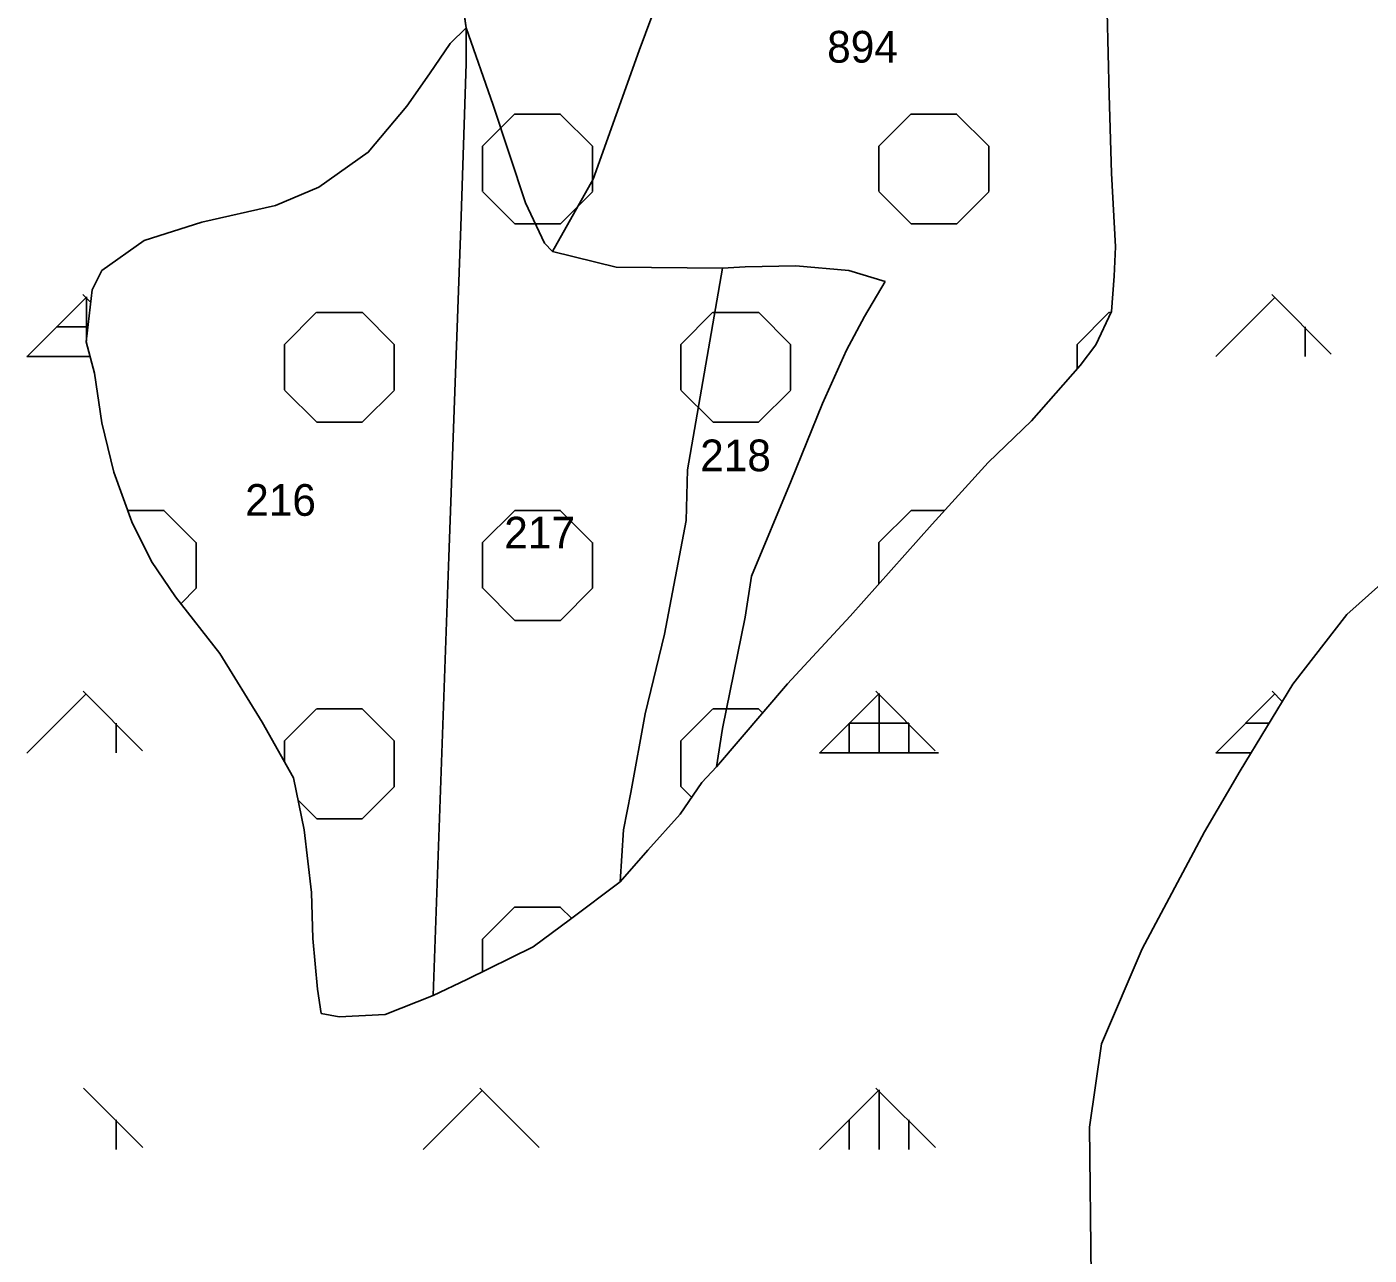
# Model space of a CAD drawing. Extents: x 410727 to 412947, y 4463506 to 4466382.
# Drawn here: x 411905.2 to 412074.5, y 4465822.5 to 4465977.4 of the extents above; entities that cross this region are included whole.
import ezdxf

# ---------------------------------------------------------------- set-up
doc = ezdxf.new("R2010")
doc.units = 0
for name, color, linetype in [('ADAKENARI', 7, 'Continuous'), ('KDS_PARSEL_NO', 7, 'Continuous'), ('KDS_PL', 7, 'Continuous'), ('PL_AYA_AGACLANDIRIL', 7, 'Continuous'), ('PL_AYA_ORMAN', 7, 'Continuous'), ('PL_KA_TARIM_DIGER', 7, 'Continuous'), ('TR_AGACALANI', 7, 'Continuous'), ('TR_ORMAN', 7, 'Continuous')]:
    doc.layers.add(name, color=color, linetype=linetype)

msp = doc.modelspace()

# ---------------------------------------------------------------- linework, layer by layer
at = {"layer": 'ADAKENARI'}
for p, q in [((411956.12, 4466009.18), (411960.57, 4465977.28)), ((412041.72, 4465968.86), (412041.46, 4465979.29)), ((411960.57, 4465977.28), (411958.56, 4465975.32)), ((411958.56, 4465975.32), (411955.98, 4465971.51)), ((411955.98, 4465971.51), (411953.09, 4465967.4)), ((412041.98, 4465958.95), (412041.72, 4465968.86)), ((411953.09, 4465967.4), (411948.23, 4465961.61)), ((411948.23, 4465961.61), (411941.99, 4465957.19)), ((412042.5, 4465949.69), (412041.98, 4465958.95)), ((411941.99, 4465957.19), (411936.52, 4465954.91)), ((411936.52, 4465954.91), (411927.25, 4465952.78)), ((411927.25, 4465952.78), (411919.95, 4465950.49)), ((411919.95, 4465950.49), (411914.63, 4465946.68)), ((412042.32, 4465946), (412042.5, 4465949.69)), ((411914.63, 4465946.68), (411913.42, 4465944.25)), ((412042.01, 4465941.51), (412042.32, 4465946)), ((411913.42, 4465944.25), (411912.66, 4465937.7)), ((412040.04, 4465937.32), (412042.01, 4465941.51)), ((411912.66, 4465937.7), (411913.72, 4465933.74)), ((412038.06, 4465934.73), (412040.04, 4465937.32)), ((412031.91, 4465927.72), (412038.06, 4465934.73)), ((411913.72, 4465933.74), (411914.63, 4465927.49)), ((411914.63, 4465927.49), (411916.15, 4465921.25)), ((412026.43, 4465922.47), (412031.91, 4465927.72)), ((412019.36, 4465914.7), (412026.43, 4465922.47)), ((411916.15, 4465921.25), (411918.43, 4465915)), ((411918.43, 4465915), (411920.87, 4465909.98)), ((412009.03, 4465903.12), (412019.36, 4465914.7)), ((411920.87, 4465909.98), (411923.91, 4465905.56)), ((412075.96, 4465907.16), (412071.69, 4465903.31)), ((411923.91, 4465905.56), (411929.53, 4465898.4)), ((412001.12, 4465894.59), (412009.03, 4465903.12)), ((412001.12, 4465894.59), (412009.03, 4465903.12)), ((412071.69, 4465903.31), (412064.86, 4465894.53)), ((411929.53, 4465898.4), (411934.85, 4465889.72)), ((411992.16, 4465884.09), (412001.12, 4465894.59)), ((412064.86, 4465894.53), (412058.24, 4465883.62)), ((411934.85, 4465889.72), (411938.8, 4465882.72)), ((411990.33, 4465882.11), (411992.16, 4465884.09)), ((412058.24, 4465883.62), (412053.75, 4465875.92)), ((411938.8, 4465882.72), (411940.17, 4465876.17)), ((411987.6, 4465878.15), (411990.33, 4465882.11)), ((411983.49, 4465873.58), (411987.6, 4465878.15)), ((411940.17, 4465876.17), (411941.08, 4465868.25)), ((412053.75, 4465875.92), (412045.85, 4465861.15)), ((411980, 4465869.62), (411983.49, 4465873.58)), ((411973.76, 4465864.9), (411980, 4465869.62)), ((411941.08, 4465868.25), (411941.23, 4465862.46)), ((411969.05, 4465861.39), (411973.76, 4465864.9)), ((411941.23, 4465862.46), (411941.84, 4465856.06)), ((411960.69, 4465857.28), (411969.05, 4465861.39)), ((412045.85, 4465861.15), (412040.72, 4465849.17)), ((411941.84, 4465856.06), (411942.3, 4465853.02)), ((411956.44, 4465855.27), (411960.69, 4465857.28)), ((411950.35, 4465852.87), (411956.44, 4465855.27)), ((411942.3, 4465853.02), (411944.58, 4465852.56)), ((411944.58, 4465852.56), (411950.35, 4465852.87)), ((412040.72, 4465849.17), (412039.23, 4465838.68)), ((412039.23, 4465838.68), (412039.44, 4465819.85))]:
    msp.add_line(p, q, dxfattribs=at)
at = {"layer": 'KDS_PL'}
for p, q in [((411960.57, 4465977.28), (411956.12, 4466009.18)), ((411982.43, 4465974.43), (411988.12, 4465989.88)), ((412041.46, 4465979.29), (412041.72, 4465968.86)), ((411958.56, 4465975.32), (411960.57, 4465977.28)), ((411960.57, 4465972.78), (411960.57, 4465977.28)), ((411960.57, 4465977.28), (411964.01, 4465967.53)), ((411955.98, 4465971.51), (411958.56, 4465975.32)), ((411976.59, 4465958.23), (411982.43, 4465974.43)), ((411953.09, 4465967.4), (411955.98, 4465971.51)), ((411959.93, 4465952.25), (411960.57, 4465972.78)), ((412041.72, 4465968.86), (412041.98, 4465958.95)), ((411948.23, 4465961.61), (411953.09, 4465967.4)), ((411964.01, 4465967.53), (411968.06, 4465955.23)), ((411941.99, 4465957.19), (411948.23, 4465961.61)), ((411971.5, 4465949.08), (411976.59, 4465958.23)), ((412041.98, 4465958.95), (412042.5, 4465949.69)), ((411936.52, 4465954.91), (411941.99, 4465957.19)), ((411927.25, 4465952.78), (411936.52, 4465954.91)), ((411968.06, 4465955.23), (411970.45, 4465950.13)), ((411919.95, 4465950.49), (411927.25, 4465952.78)), ((411958.38, 4465910.58), (411959.93, 4465952.25)), ((411914.63, 4465946.68), (411919.95, 4465950.49)), ((411970.45, 4465950.13), (411971.5, 4465949.08)), ((412042.5, 4465949.69), (412042.32, 4465946)), ((411979.51, 4465947.13), (411971.5, 4465949.08)), ((411913.42, 4465944.25), (411914.63, 4465946.68)), ((411992.92, 4465946.99), (411979.51, 4465947.13)), ((411992.92, 4465946.99), (411988.51, 4465921.55)), ((411995.8, 4465947.14), (411992.92, 4465946.99)), ((412002.19, 4465947.29), (411995.8, 4465947.14)), ((412008.88, 4465946.68), (412002.19, 4465947.29)), ((412013.44, 4465945.31), (412008.88, 4465946.68)), ((412042.32, 4465946), (412042.01, 4465941.51)), ((411912.66, 4465937.7), (411913.42, 4465944.25)), ((412010.85, 4465940.9), (412013.44, 4465945.31)), ((412008.57, 4465936.63), (412010.85, 4465940.9)), ((412042.01, 4465941.51), (412040.04, 4465937.32)), ((411913.72, 4465933.74), (411912.66, 4465937.7)), ((412040.04, 4465937.32), (412038.06, 4465934.73)), ((412005.53, 4465929.93), (412008.57, 4465936.63)), ((412038.06, 4465934.73), (412031.91, 4465927.72)), ((411914.63, 4465927.49), (411913.72, 4465933.74)), ((412001.58, 4465920.18), (412005.53, 4465929.93)), ((411916.15, 4465921.25), (411914.63, 4465927.49)), ((412031.91, 4465927.72), (412026.43, 4465922.47)), ((412026.43, 4465922.47), (412019.36, 4465914.7)), ((411918.43, 4465915), (411916.15, 4465921.25)), ((411988.51, 4465921.55), (411988.36, 4465915.16)), ((411996.57, 4465908.15), (412001.58, 4465920.18)), ((411920.87, 4465909.98), (411918.43, 4465915)), ((411988.36, 4465915.16), (411985.62, 4465900.84)), ((412019.36, 4465914.7), (412009.03, 4465903.12)), ((411956.44, 4465855.27), (411958.38, 4465910.58)), ((411923.91, 4465905.56), (411920.87, 4465909.98)), ((411995.8, 4465902.97), (411996.57, 4465908.15)), ((412075.96, 4465907.16), (412071.69, 4465903.31)), ((411929.53, 4465898.4), (411923.91, 4465905.56)), ((411992.92, 4465888.96), (411995.8, 4465902.97)), ((412009.03, 4465903.12), (412001.12, 4465894.59)), ((412071.69, 4465903.31), (412064.86, 4465894.53)), ((411985.62, 4465900.84), (411983.19, 4465890.79)), ((411934.85, 4465889.72), (411929.53, 4465898.4)), ((412001.12, 4465894.59), (411992.16, 4465884.09)), ((412064.86, 4465894.53), (412058.24, 4465883.62)), ((411983.19, 4465890.79), (411981.36, 4465880.89)), ((411938.8, 4465882.72), (411934.85, 4465889.72)), ((411992.16, 4465884.09), (411992.92, 4465888.96)), ((411990.33, 4465882.11), (411992.16, 4465884.09)), ((412058.24, 4465883.62), (412053.75, 4465875.92)), ((411940.17, 4465876.17), (411938.8, 4465882.72)), ((411987.6, 4465878.15), (411990.33, 4465882.11)), ((411981.36, 4465880.89), (411980.45, 4465876.17)), ((411983.49, 4465873.58), (411987.6, 4465878.15)), ((411941.08, 4465868.25), (411940.17, 4465876.17)), ((411980.45, 4465876.17), (411980, 4465869.62)), ((412053.75, 4465875.92), (412045.85, 4465861.15)), ((411980, 4465869.62), (411983.49, 4465873.58)), ((411980, 4465869.62), (411973.76, 4465864.9)), ((411941.23, 4465862.46), (411941.08, 4465868.25)), ((411973.76, 4465864.9), (411969.05, 4465861.39)), ((411941.84, 4465856.06), (411941.23, 4465862.46)), ((411969.05, 4465861.39), (411960.69, 4465857.28)), ((412045.85, 4465861.15), (412040.72, 4465849.17)), ((411942.3, 4465853.02), (411941.84, 4465856.06)), ((411960.69, 4465857.28), (411956.44, 4465855.27)), ((411956.44, 4465855.27), (411950.35, 4465852.87)), ((411944.58, 4465852.56), (411942.3, 4465853.02)), ((411950.35, 4465852.87), (411944.58, 4465852.56)), ((412040.72, 4465849.17), (412039.23, 4465838.68)), ((412039.23, 4465838.68), (412039.44, 4465819.85))]:
    msp.add_line(p, q, dxfattribs=at)
at = {"layer": 'PL_AYA_AGACLANDIRIL'}
msp.add_lwpolyline([(412041.46, 4465979.29), (412041.72, 4465968.86), (412041.98, 4465958.95), (412042.5, 4465949.69), (412042.32, 4465946), (412042.01, 4465941.51), (412040.04, 4465937.32), (412038.06, 4465934.73), (412031.91, 4465927.72), (412026.43, 4465922.47), (412019.36, 4465914.7), (412009.03, 4465903.12), (412001.12, 4465894.59), (411992.16, 4465884.09), (411990.33, 4465882.11), (411987.6, 4465878.15), (411983.49, 4465873.58), (411980, 4465869.62), (411973.76, 4465864.9), (411969.05, 4465861.39), (411960.69, 4465857.28), (411956.44, 4465855.27), (411950.35, 4465852.87), (411944.58, 4465852.56), (411942.3, 4465853.02), (411941.84, 4465856.06), (411941.23, 4465862.46), (411941.08, 4465868.25), (411940.17, 4465876.17), (411938.8, 4465882.72), (411934.85, 4465889.72), (411929.53, 4465898.4), (411923.91, 4465905.56), (411920.87, 4465909.98), (411918.43, 4465915), (411916.15, 4465921.25), (411914.63, 4465927.49), (411913.72, 4465933.74), (411912.66, 4465937.7), (411913.42, 4465944.25), (411914.63, 4465946.68), (411919.95, 4465950.49), (411927.25, 4465952.78), (411936.52, 4465954.91), (411941.99, 4465957.19), (411948.23, 4465961.61), (411953.09, 4465967.4), (411955.98, 4465971.51), (411958.56, 4465975.32), (411960.57, 4465977.28), (411956.12, 4466009.18)], dxfattribs=at)
at = {"layer": 'PL_AYA_ORMAN'}
for points in [[(412041.46, 4465979.29), (412041.72, 4465968.86), (412041.98, 4465958.95), (412042.5, 4465949.69), (412042.32, 4465946), (412042.01, 4465941.51), (412040.04, 4465937.32), (412038.06, 4465934.73), (412031.91, 4465927.72), (412026.43, 4465922.47), (412019.36, 4465914.7), (412009.03, 4465903.12), (412001.12, 4465894.59), (411992.16, 4465884.09), (411990.33, 4465882.11), (411987.6, 4465878.15), (411983.49, 4465873.58), (411980, 4465869.62), (411973.76, 4465864.9), (411969.05, 4465861.39), (411960.69, 4465857.28), (411956.44, 4465855.27), (411950.35, 4465852.87), (411944.58, 4465852.56), (411942.3, 4465853.02), (411941.84, 4465856.06), (411941.23, 4465862.46), (411941.08, 4465868.25), (411940.17, 4465876.17), (411938.8, 4465882.72), (411934.85, 4465889.72), (411929.53, 4465898.4), (411923.91, 4465905.56), (411920.87, 4465909.98), (411918.43, 4465915), (411916.15, 4465921.25), (411914.63, 4465927.49), (411913.72, 4465933.74), (411912.66, 4465937.7), (411913.42, 4465944.25), (411914.63, 4465946.68), (411919.95, 4465950.49), (411927.25, 4465952.78), (411936.52, 4465954.91), (411941.99, 4465957.19), (411948.23, 4465961.61), (411953.09, 4465967.4), (411955.98, 4465971.51), (411958.56, 4465975.32), (411960.57, 4465977.28), (411956.12, 4466009.18)], [(412039.44, 4465819.85), (412039.23, 4465838.68), (412040.72, 4465849.17), (412045.85, 4465861.15), (412053.75, 4465875.92), (412058.24, 4465883.62), (412064.86, 4465894.53), (412071.69, 4465903.31), (412075.96, 4465907.16)]]:
    msp.add_lwpolyline(points, dxfattribs=at)
at = {"layer": 'PL_KA_TARIM_DIGER'}
msp.add_lwpolyline([(412039.44, 4465819.85), (412039.23, 4465838.68), (412040.72, 4465849.17), (412045.85, 4465861.15), (412053.75, 4465875.92), (412058.24, 4465883.62), (412064.86, 4465894.53), (412071.69, 4465903.31), (412075.96, 4465907.16)], dxfattribs=at)
at = {"layer": 'TR_AGACALANI'}
for p, q in [((411962.66, 4465962.38), (411966.72, 4465966.44)), ((411966.74, 4465966.42), (411972.48, 4465966.42)), ((411976.52, 4465962.37), (411972.46, 4465966.43)), ((412012.66, 4465962.38), (412016.72, 4465966.44)), ((412016.74, 4465966.42), (412022.48, 4465966.42)), ((412026.52, 4465962.37), (412022.46, 4465966.43)), ((411962.66, 4465956.64), (411962.66, 4465962.38)), ((411976.52, 4465956.64), (411976.52, 4465962.38)), ((412012.66, 4465956.64), (412012.66, 4465962.38)), ((412026.52, 4465956.64), (412026.52, 4465962.38)), ((411966.74, 4465952.56), (411962.68, 4465956.62)), ((411972.48, 4465952.56), (411976.54, 4465956.62)), ((412016.74, 4465952.56), (412012.68, 4465956.62)), ((412022.48, 4465952.56), (412026.54, 4465956.62)), ((411966.74, 4465952.56), (411972.48, 4465952.56)), ((412016.74, 4465952.56), (412022.48, 4465952.56)), ((411937.66, 4465937.38), (411941.72, 4465941.44)), ((411941.74, 4465941.42), (411947.48, 4465941.42)), ((411951.52, 4465937.37), (411947.46, 4465941.43)), ((411987.66, 4465937.38), (411991.72, 4465941.44)), ((411991.74, 4465941.42), (411997.48, 4465941.42)), ((412001.52, 4465937.37), (411997.46, 4465941.43)), ((412037.66, 4465937.38), (412041.72, 4465941.44)), ((412041.74, 4465941.42), (412041.97, 4465941.42)), ((411937.66, 4465931.64), (411937.66, 4465937.38)), ((411951.52, 4465931.64), (411951.52, 4465937.38)), ((411987.66, 4465931.64), (411987.66, 4465937.38)), ((412001.52, 4465931.64), (412001.52, 4465937.38)), ((412037.66, 4465934.27), (412037.66, 4465937.38)), ((411941.74, 4465927.56), (411937.68, 4465931.62)), ((411947.48, 4465927.56), (411951.54, 4465931.62)), ((411991.74, 4465927.56), (411987.68, 4465931.62)), ((411997.48, 4465927.56), (412001.54, 4465931.62)), ((411941.74, 4465927.56), (411947.48, 4465927.56)), ((411991.74, 4465927.56), (411997.48, 4465927.56)), ((411917.92, 4465916.42), (411922.48, 4465916.42)), ((411926.52, 4465912.37), (411922.46, 4465916.43)), ((411962.66, 4465912.38), (411966.72, 4465916.44)), ((411966.74, 4465916.42), (411972.48, 4465916.42)), ((411976.52, 4465912.37), (411972.46, 4465916.43)), ((412012.66, 4465912.38), (412016.72, 4465916.44)), ((412016.74, 4465916.42), (412020.93, 4465916.42)), ((411926.52, 4465906.64), (411926.52, 4465912.38)), ((411962.66, 4465906.64), (411962.66, 4465912.38)), ((411976.52, 4465906.64), (411976.52, 4465912.38)), ((412012.66, 4465907.19), (412012.66, 4465912.38)), ((411924.6, 4465904.68), (411926.54, 4465906.62)), ((411966.74, 4465902.56), (411962.68, 4465906.62)), ((411972.48, 4465902.56), (411976.54, 4465906.62)), ((411966.74, 4465902.56), (411972.48, 4465902.56)), ((411937.66, 4465887.38), (411941.72, 4465891.44)), ((411941.74, 4465891.42), (411947.48, 4465891.42)), ((411951.52, 4465887.38), (411947.46, 4465891.43)), ((411987.66, 4465887.38), (411991.72, 4465891.44)), ((411991.74, 4465891.42), (411997.48, 4465891.42)), ((411997.98, 4465890.91), (411997.46, 4465891.43)), ((411937.66, 4465884.75), (411937.66, 4465887.38)), ((411951.52, 4465881.64), (411951.52, 4465887.38)), ((411987.66, 4465881.64), (411987.66, 4465887.38)), ((411947.48, 4465877.56), (411951.54, 4465881.62)), ((411989.05, 4465880.25), (411987.68, 4465881.62)), ((411941.74, 4465877.56), (411939.39, 4465879.91)), ((411941.74, 4465877.56), (411947.48, 4465877.56)), ((411962.66, 4465862.38), (411966.72, 4465866.44)), ((411966.74, 4465866.42), (411972.48, 4465866.42)), ((411973.9, 4465865), (411972.46, 4465866.43)), ((411962.66, 4465858.25), (411962.66, 4465862.38))]:
    msp.add_line(p, q, dxfattribs=at)
at = {"layer": 'TR_ORMAN'}
for p, q in [((411905.16, 4465935.81), (411912.66, 4465943.31)), ((411913.23, 4465942.66), (411912.24, 4465943.65)), ((411913.23, 4465942.66), (411912.24, 4465943.65)), ((411912.67, 4465937.78), (411912.67, 4465943.36)), ((412055.16, 4465935.83), (412062.66, 4465943.33)), ((412069.72, 4465936.15), (412062.22, 4465943.65)), ((412069.72, 4465936.15), (412062.22, 4465943.65)), ((411908.92, 4465939.61), (411912.88, 4465939.61)), ((412066.42, 4465935.86), (412066.42, 4465939.61)), ((411905.17, 4465935.86), (411913.15, 4465935.86)), ((411905.16, 4465885.82), (411912.66, 4465893.32)), ((411919.77, 4465886.13), (411912.27, 4465893.63)), ((411919.77, 4465886.13), (411912.27, 4465893.63)), ((412005.16, 4465885.83), (412012.66, 4465893.33)), ((412019.76, 4465886.13), (412012.26, 4465893.63)), ((412012.67, 4465885.86), (412012.67, 4465893.36)), ((412055.16, 4465885.84), (412062.66, 4465893.34)), ((412063.53, 4465892.35), (412062.25, 4465893.63)), ((411916.42, 4465885.86), (411916.42, 4465889.61)), ((412008.92, 4465885.86), (412008.92, 4465889.61)), ((412008.92, 4465889.61), (412016.42, 4465889.61)), ((412016.42, 4465885.86), (412016.42, 4465889.61)), ((412058.92, 4465889.61), (412061.87, 4465889.61)), ((412005.17, 4465885.86), (412020.17, 4465885.86)), ((412055.17, 4465885.86), (412059.6, 4465885.86)), ((411919.8, 4465836.1), (411912.31, 4465843.6)), ((411919.8, 4465836.1), (411912.31, 4465843.6)), ((411955.16, 4465835.83), (411962.66, 4465843.33)), ((411969.8, 4465836.1), (411962.3, 4465843.6)), ((412005.16, 4465835.84), (412012.66, 4465843.34)), ((412019.79, 4465836.1), (412012.29, 4465843.6)), ((412012.67, 4465835.86), (412012.67, 4465843.36)), ((411916.42, 4465835.86), (411916.42, 4465839.61)), ((412008.92, 4465835.86), (412008.92, 4465839.61)), ((412016.42, 4465835.86), (412016.42, 4465839.61))]:
    msp.add_line(p, q, dxfattribs=at)

# ---------------------------------------------------------------- texts
at = {"layer": 'KDS_PARSEL_NO'}
for s, p in [('894', (412006.13, 4465972.91)), ('218', (411990.11, 4465921.38)), ('216', (411932.71, 4465915.76)), ('217', (411965.39, 4465911.64))]:
    msp.add_text(s, height=4, dxfattribs=at).set_placement(p)

doc.saveas('drawing.dxf')
